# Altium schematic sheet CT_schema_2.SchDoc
size 200 x 173 mm
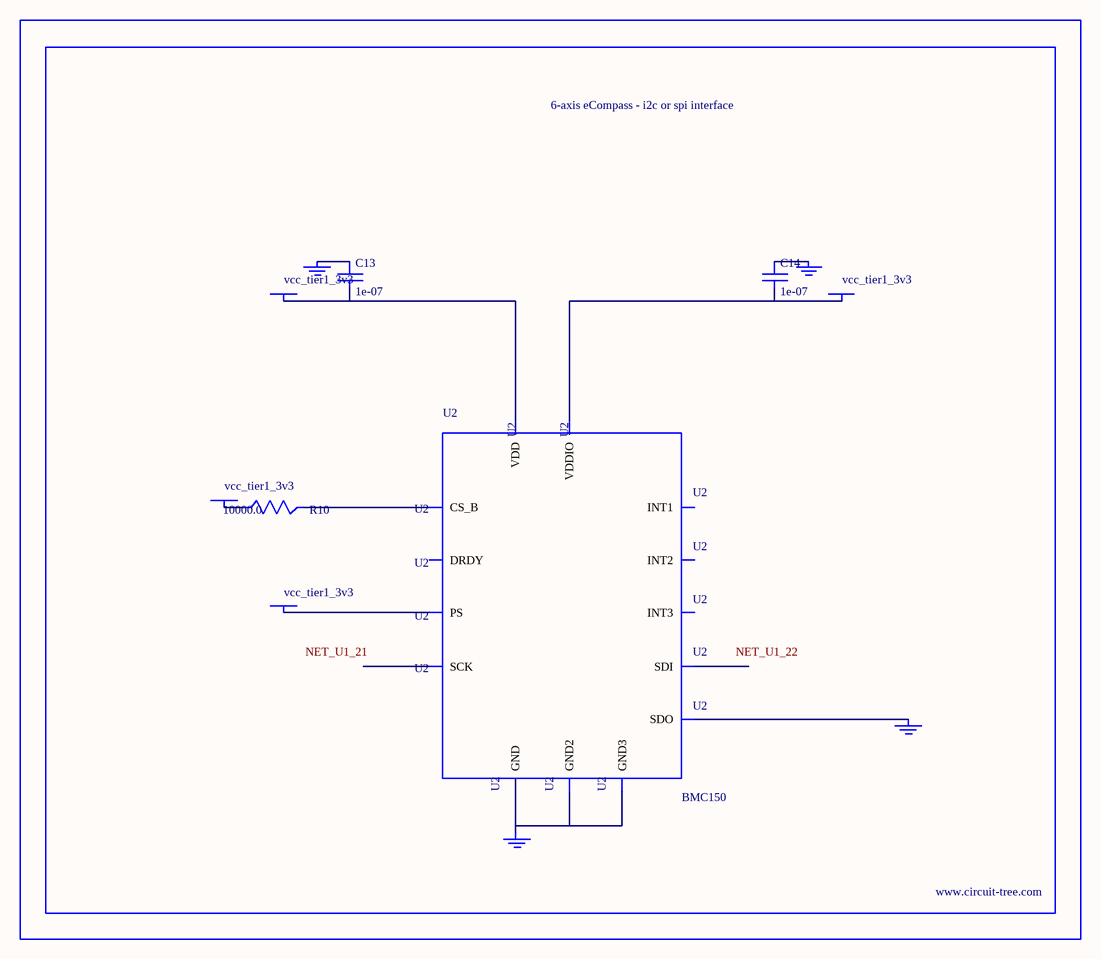
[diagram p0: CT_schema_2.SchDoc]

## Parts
BORDER1  (no value)
C13  1e-07  [C0402]
C14  1e-07  [C0402]
GND_INSTANCE_1_0  (no value)
GND_INSTANCE_1_1  (no value)
GND_INSTANCE_1_2  (no value)
GND_INSTANCE_1_3  (no value)
POWER_INSTANCE_1_0  vcc_tier1_3v3
POWER_INSTANCE_1_1  vcc_tier1_3v3
POWER_INSTANCE_1_2  vcc_tier1_3v3
POWER_INSTANCE_1_3  vcc_tier1_3v3
R10  10000.0  [R0603]
U2  BMC150  [LGA14R35P5X6_200X200X100]

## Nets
NetC13_1: C13.1 GND_INSTANCE_1_1.0(GND)
NetC13_2: C13.2 POWER_INSTANCE_1_0.0(PWR) U2.8(VDD)
NetC14_1: C14.1 GND_INSTANCE_1_2.0(GND)
NetC14_2: C14.2 POWER_INSTANCE_1_1.0(PWR) U2.10(VDDIO)
NetGND_INSTANCE_1_0_0: GND_INSTANCE_1_0.0(GND) U2.1(SDO)
NetGND_INSTANCE_1_3_0: GND_INSTANCE_1_3.0(GND) U2.6(GND) U2.7(GND2) U2.9(GND3)
NetPOWER_INSTANCE_1_2_0: POWER_INSTANCE_1_2.0(PWR) R10.1
NetPOWER_INSTANCE_1_3_0: POWER_INSTANCE_1_3.0(PWR) U2.13(PS)
NetR10_2: R10.2 U2.12(CS_B)

Not connected (* = marked no-connect by the designer): U2 2(INT1) 3(INT2) 4(DRDY) 5(INT3) 11(SCK) 14(SDI)

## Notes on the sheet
- Labels drawn without touching a wire or pin: NET_U1_21, NET_U1_22

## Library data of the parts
BORDER1 = BORDER_PAGE1
C13 C14 = C0402C104K3RACTU
GND_INSTANCE_1_0-GND_INSTANCE_1_3 = GND
POWER_INSTANCE_1_0-POWER_INSTANCE_1_3 = PWR
R10 = RC0603JR-0710KL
